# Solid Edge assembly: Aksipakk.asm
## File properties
Author: morva
Template: iso metric assembly.asm
Last saved by: morva
Revision: 8
Application: Solid Edge
Username: morva
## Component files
18650_battery.par
AksiprotectionDummy.par
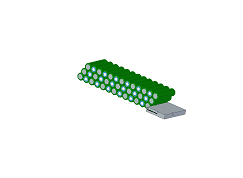
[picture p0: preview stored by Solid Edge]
